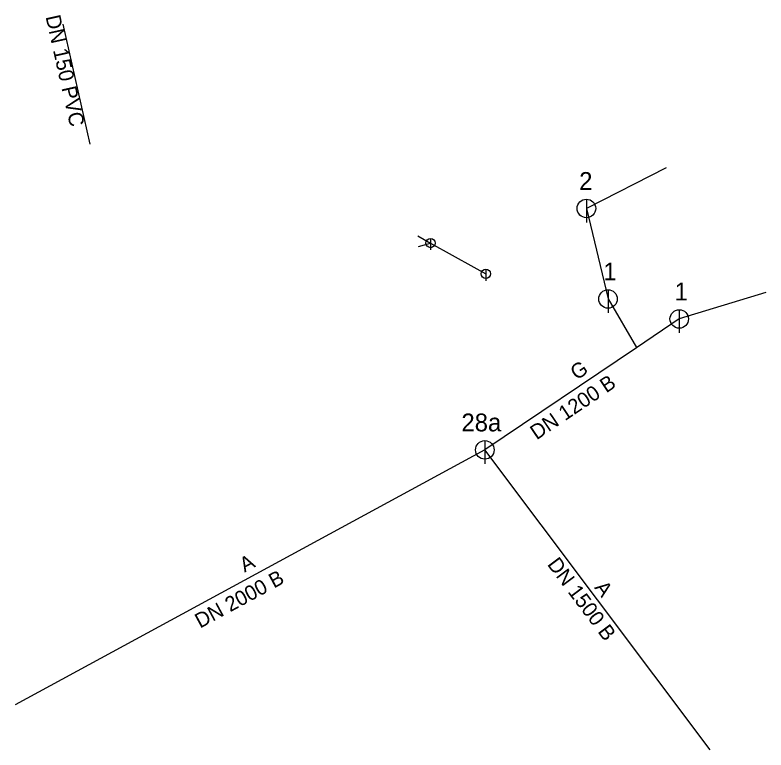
# Model space of a CAD drawing. Extents: x -451691.2 to -451610.1, y -1100714.2 to -1100634.8.
import ezdxf

# ---------------------------------------------------------------- set-up
doc = ezdxf.new("R2010")
doc.units = 0
for name, color, linetype in [('_pripojka_kanal_jednotna_prevzato_z_dokumentace_', 7, 'Continuous'), ('_pripojka_kanal_jednotna_priblizne_', 7, 'Continuous'), ('_stoka_jednotna_smvak_prevzato_z_dokumentace_', 7, 'Continuous'), ('Default', 7, 'Continuous'), ('MoLevel 119', 7, 'Continuous'), ('MoLevel 120', 7, 'Continuous'), ('MoLevel 124', 7, 'Continuous'), ('MoLevel 57', 7, 'Continuous'), ('MoLevel 68', 7, 'Continuous'), ('MoLevel 69', 7, 'Continuous')]:
    doc.layers.add(name, color=color, linetype=linetype)

# ---------------------------------------------------------------- blocks, each defined once
blk = doc.blocks.new('_sachta_kanal_prip_')
at = {"layer": 'Default'}
blk.add_line((0, 0.00005), (0, -0.000075), dxfattribs=at)
blk.add_circle((0, 0), 0.00005, dxfattribs=at)
blk = doc.blocks.new('_sachta_kanal_prevzato_z_dokumentace_')
at = {"layer": 'Default'}
blk.add_line((0, 0.00005), (0, -0.000075), dxfattribs=at)
blk.add_circle((0, 0), 0.00005, dxfattribs=at)

msp = doc.modelspace()

# ---------------------------------------------------------------- linework, layer by layer
at = {"layer": '_pripojka_kanal_jednotna_prevzato_z_dokumentace_'}
msp.add_line((-451647.645, -1100659.797), (-451646.35, -1100659.44), dxfattribs=at)
msp.add_lwpolyline([(-451647.736, -1100658.66), (-451646.35, -1100659.44), (-451641.691, -1100662.031), (-451640.38, -1100662.76)], dxfattribs=at)
at = {"layer": '_pripojka_kanal_jednotna_priblizne_'}
msp.add_line((-451683.098, -1100648.765), (-451685.995, -1100635.814), dxfattribs=at)
at = {"layer": '_stoka_jednotna_smvak_prevzato_z_dokumentace_'}
for p, q in [((-451620.912, -1100651.319), (-451629.525, -1100655.707)), ((-451629.525, -1100655.707), (-451627.189, -1100665.477)), ((-451610.142, -1100664.782), (-451619.506, -1100667.637)), ((-451627.189, -1100665.477), (-451624.135, -1100670.733)), ((-451619.506, -1100667.637), (-451624.125, -1100670.748)), ((-451624.125, -1100670.748), (-451640.49, -1100681.77)), ((-451640.49, -1100681.77), (-451691.2, -1100709.27)), ((-451616.17, -1100714.16), (-451640.49, -1100681.77))]:
    msp.add_line(p, q, dxfattribs=at)

# ---------------------------------------------------------------- block references
at = {"layer": 'MoLevel 119', "xscale": 20000, "yscale": 20000}
for p in [(-451629.525, -1100655.707), (-451627.189, -1100665.477), (-451619.506, -1100667.637), (-451640.49, -1100681.77)]:
    msp.add_blockref('_sachta_kanal_prevzato_z_dokumentace_', p, dxfattribs=at)
at = {"layer": 'MoLevel 57', "xscale": 10000, "yscale": 10000}
for p in [(-451646.35, -1100659.44), (-451640.38, -1100662.76)]:
    msp.add_blockref('_sachta_kanal_prip_', p, dxfattribs=at)

# ---------------------------------------------------------------- texts
at = {"layer": 'MoLevel 120'}
for s, height, p in [('2', 1.926, (-451630.305, -1100653.707)), ('1', 1.926, (-451627.693, -1100663.477)), ('1', 1.926, (-451620.01, -1100665.637)), ('28a', 1.9259, (-451643.012, -1100679.77))]:
    msp.add_text(s, height=height, dxfattribs=at).set_placement(p)
at = {"layer": 'MoLevel 124'}
msp.add_text('DN 150 PVC', height=1.6049, rotation=282.61161, dxfattribs=at).set_placement((-451687.912, -1100635.006))
at = {"layer": 'MoLevel 68'}
for s, rotation, p in [('DN 1200 B', 33.96079, (-451634.902, -1100680.741)), ('DN 1500 B', 306.90102, (-451633.812, -1100694.137)), ('DN 2000 B', 28.47095, (-451671.227, -1100701.064))]:
    msp.add_text(s, height=1.6049, rotation=rotation, dxfattribs=at).set_placement(p)
at = {"layer": 'MoLevel 69'}
for s, rotation, p in [('G', 33.96079, (-451630.569, -1100674.288)), ('A', 28.47095, (-451666.416, -1100695.03)), ('A', 306.90102, (-451628.72, -1100696.646))]:
    msp.add_text(s, height=1.605, rotation=rotation, dxfattribs=at).set_placement(p)

doc.saveas('drawing.dxf')
